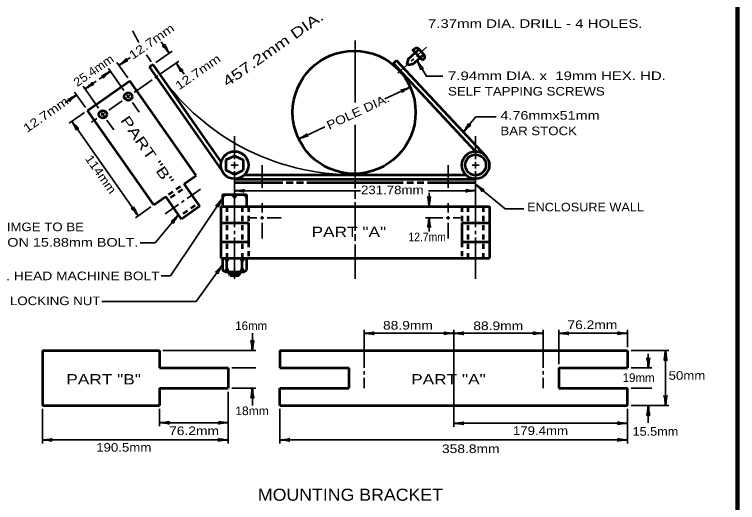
# Model space of a CAD drawing. Extents: x -33 to 680, y -7 to 447.
# Drawn here: x 464.8 to 674.8, y 130.8 to 272.6 of the extents above; entities that cross this region are included whole.
import ezdxf

# ---------------------------------------------------------------- set-up
doc = ezdxf.new("R2010")
doc.units = 0
doc.linetypes.add('SHORT_DASHED', pattern=[2.7, 1.5, -1.2])
doc.layers.add('1', color=7, linetype='Continuous', lineweight=53)

msp = doc.modelspace()

# ---------------------------------------------------------------- linework, layer by layer
at = {"layer": '1', "lineweight": 158}
msp.add_line((674.767, 2.994), (674.767, 441.411), dxfattribs=at)
at = {"layer": '1', "lineweight": 13}
msp.add_line((674.767, 2.994), (674.767, 441.411), dxfattribs=at)
at = {"layer": '1', "lineweight": 35}
for p, q in [((507.412, 264.673), (509.706, 261.396)), ((563.683, 247.071), (563.683, 265.073)), ((581.861, 260.776), (584.461, 263.118)), ((510.525, 261.97), (505.815, 258.672)), ((581.489, 260.442), (581.861, 260.776)), ((497.664, 254.185), (494.51, 258.691)), ((495.083, 257.872), (498.36, 260.166)), ((507.208, 255.375), (512.533, 259.103)), ((511.714, 258.529), (514.008, 255.253)), ((578.887, 258.099), (579.259, 258.434)), ((580.002, 259.103), (580.746, 259.772)), ((496.567, 250.522), (492.052, 256.97)), ((576.101, 255.59), (578.887, 258.099)), ((489.349, 253.857), (492.626, 256.151)), ((505.57, 254.228), (506.389, 254.801)), ((485.253, 250.989), (488.53, 253.283)), ((499.529, 249.998), (504.751, 253.654)), ((485.377, 245.582), (482.222, 250.087)), ((489.192, 245.363), (484.68, 251.808)), ((572.353, 248.101), (579.707, 251.53)), ((479.519, 246.974), (482.796, 249.268)), ((497.277, 248.421), (498.301, 249.138)), ((498.145, 248.269), (497.428, 249.293)), ((492.159, 244.837), (496.048, 247.56)), ((500.942, 244.273), (499.005, 247.04)), ((480.626, 241.034), (485.132, 244.189)), ((489.906, 243.26), (490.93, 243.977)), ((490.77, 243.11), (490.053, 244.134)), ((481.445, 241.608), (500.701, 214.108)), ((487.139, 241.322), (488.678, 242.4)), ((493.57, 239.111), (491.63, 241.882)), ((547.32, 236.428), (554.868, 239.948)), ((563.683, 226.043), (563.683, 240.605)), ((528.683, 237.293), (528.683, 230.593)), ((598.683, 237.293), (598.683, 230.593)), ((528.683, 229.843), (528.683, 227.843)), ((598.683, 229.843), (598.683, 227.843)), ((527.683, 228.843), (529.683, 228.843)), ((536.683, 222.293), (536.683, 228.793)), ((590.683, 222.293), (590.683, 228.793)), ((597.683, 228.843), (599.683, 228.843)), ((598.683, 227.093), (598.683, 210.793)), ((563.683, 226.043), (563.683, 222.043)), ((514.873, 219.148), (518.764, 221.872)), ((528.683, 221.397), (565.267, 221.397)), ((563.683, 221.043), (563.683, 219.043)), ((584.998, 221.397), (598.683, 221.397)), ((585.183, 216.793), (585.183, 220.793)), ((525.183, 219.224), (510.108, 196.647)), ((513.235, 218.001), (514.054, 218.574)), ((528.683, 220.293), (528.683, 210.793)), ((499.882, 213.534), (504.387, 216.689)), ((508.525, 214.703), (512.416, 217.427)), ((536.683, 217.793), (536.683, 215.043)), ((563.683, 218.043), (563.683, 209.793)), ((590.683, 217.793), (590.683, 215.043)), ((512.396, 214.404), (505.588, 206.275)), ((533.183, 213.543), (535.183, 213.543)), ((536.183, 213.543), (537.183, 213.543)), ((536.683, 214.043), (536.683, 213.043)), ((538.183, 213.543), (542.183, 213.543)), ((584.183, 213.543), (589.183, 213.543)), ((585.183, 213.543), (585.183, 209.543)), ((590.183, 213.543), (591.183, 213.543)), ((590.683, 214.043), (590.683, 213.043)), ((592.183, 213.543), (594.183, 213.543)), ((536.683, 212.043), (536.683, 207.543)), ((590.683, 212.043), (590.683, 207.543)), ((528.683, 209.793), (528.683, 208.793)), ((563.683, 208.793), (563.683, 206.793)), ((598.683, 209.793), (598.683, 208.793)), ((505.588, 206.275), (501.251, 206.275)), ((528.683, 207.793), (528.683, 195.793)), ((598.683, 207.793), (598.683, 195.793)), ((563.683, 205.793), (563.683, 195.793)), ((525.183, 199.873), (517.556, 189.163)), ((510.108, 196.647), (507.318, 196.647)), ((517.556, 189.163), (490.164, 189.163)), ((566.352, 180.965), (566.352, 169.965)), ((592.352, 180.965), (592.352, 152.798)), ((618.352, 180.965), (618.352, 169.965)), ((622.852, 170.965), (622.852, 180.965)), ((642.852, 175.965), (642.852, 180.965)), ((533.852, 174.965), (533.852, 179.965)), ((622.852, 179.965), (642.852, 179.965)), ((507.852, 174.965), (534.852, 174.965)), ((643.852, 174.965), (654.852, 174.965)), ((653.852, 174.965), (653.852, 158.965)), ((648.852, 173.965), (648.852, 169.965)), ((527.852, 169.965), (534.852, 169.965)), ((566.352, 168.965), (566.352, 167.965)), ((618.352, 168.965), (618.352, 167.965)), ((643.852, 169.965), (649.852, 169.965)), ((566.352, 166.965), (566.352, 163.965)), ((618.352, 166.965), (618.352, 163.965)), ((527.852, 163.965), (534.852, 163.965)), ((533.852, 163.965), (533.852, 158.965)), ((643.852, 163.965), (649.852, 163.965)), ((526.852, 162.965), (526.852, 147.965)), ((472.852, 157.965), (472.852, 147.965)), ((506.852, 157.965), (506.852, 152.965)), ((541.852, 157.965), (541.852, 147.965)), ((642.852, 157.965), (642.852, 147.965)), ((643.852, 158.965), (654.852, 158.965)), ((648.852, 158.965), (648.852, 153.965)), ((506.852, 153.965), (526.852, 153.965)), ((592.352, 153.798), (642.852, 153.798)), ((472.852, 148.965), (526.852, 148.965)), ((541.852, 148.965), (642.852, 148.965))]:
    msp.add_line(p, q, dxfattribs=at)
at = {"layer": '1'}
for p, q in [((579.135, 259.668), (582.293, 262.512)), ((580.499, 258.205), (583.658, 261.049)), ((583.658, 261.049), (582.294, 262.512)), ((574.813, 258.437), (575.727, 259.29)), ((598.683, 232.84), (574.813, 258.437)), ((601.849, 231.277), (575.727, 259.29)), ((579.135, 259.668), (578.717, 258.282)), ((583.225, 259.313), (583.746, 259.783)), ((504.996, 258.099), (503.972, 257.382)), ((524.949, 227.424), (503.972, 257.382)), ((524.817, 229.791), (504.996, 258.099)), ((579.058, 257.916), (578.717, 258.282)), ((580.499, 258.205), (579.058, 257.916)), ((485.951, 244.763), (498.238, 253.366)), ((517.494, 225.866), (498.238, 253.366)), ((505.207, 217.262), (485.951, 244.763)), ((526.183, 230.343), (526.183, 227.343)), ((531.183, 230.343), (531.183, 227.343)), ((528.683, 226.093), (526.183, 227.343)), ((528.683, 226.093), (531.183, 227.343)), ((514.012, 223.428), (517.494, 225.866)), ((528.683, 224.793), (598.683, 224.793)), ((518.601, 216.875), (514.012, 223.428)), ((528.683, 223.793), (542.683, 223.793)), ((543.683, 223.793), (545.683, 223.793)), ((546.683, 223.793), (548.683, 223.793)), ((578.683, 223.793), (580.683, 223.793)), ((581.683, 223.793), (583.683, 223.793)), ((584.683, 223.793), (598.683, 223.793)), ((505.207, 217.262), (508.688, 219.7)), ((513.276, 213.147), (508.688, 219.7)), ((525.183, 220.293), (525.183, 216.793)), ((525.183, 219.293), (525.933, 220.293)), ((531.433, 220.293), (532.183, 219.293)), ((532.183, 220.293), (532.183, 216.793)), ((518.601, 216.875), (513.276, 213.147)), ((524.683, 216.793), (602.683, 216.793)), ((524.683, 216.793), (524.683, 201.793)), ((602.683, 216.793), (602.683, 201.793)), ((524.683, 212.043), (532.683, 212.043)), ((532.683, 212.043), (532.683, 206.543)), ((594.683, 212.043), (602.683, 212.043)), ((594.683, 212.043), (594.683, 206.543)), ((524.683, 206.543), (532.683, 206.543)), ((594.683, 206.543), (602.683, 206.543)), ((524.683, 201.793), (602.683, 201.793)), ((525.183, 201.793), (525.183, 198.293)), ((532.183, 201.793), (532.183, 198.293)), ((526.433, 198.793), (526.433, 200.793)), ((530.933, 198.793), (530.933, 200.793)), ((525.183, 198.293), (525.933, 197.793)), ((525.933, 197.793), (526.933, 197.793)), ((526.933, 197.793), (530.433, 197.793)), ((527.433, 196.793), (526.933, 197.793)), ((529.933, 196.793), (530.433, 197.793)), ((530.433, 197.793), (531.433, 197.793)), ((531.433, 197.793), (532.183, 198.293)), ((527.183, 197.293), (530.183, 197.293)), ((527.433, 196.793), (529.933, 196.793)), ((472.852, 174.965), (506.852, 174.965)), ((472.852, 174.965), (472.852, 158.965)), ((506.852, 174.965), (506.852, 169.965)), ((541.852, 174.965), (541.852, 169.965)), ((541.852, 174.965), (642.852, 174.965)), ((642.852, 174.965), (642.852, 169.965)), ((506.852, 169.965), (526.852, 169.965)), ((526.852, 169.965), (526.852, 163.965)), ((541.852, 169.965), (561.852, 169.965)), ((561.852, 169.965), (561.852, 163.965)), ((622.852, 169.965), (642.852, 169.965)), ((622.852, 169.965), (622.852, 163.965)), ((506.852, 163.965), (526.852, 163.965)), ((506.852, 163.965), (506.852, 158.965)), ((541.852, 163.965), (561.852, 163.965)), ((541.852, 158.965), (541.852, 163.965)), ((622.852, 163.965), (642.852, 163.965)), ((642.852, 158.965), (642.852, 163.965)), ((472.852, 158.965), (506.852, 158.965)), ((541.852, 158.965), (642.852, 158.965))]:
    msp.add_line(p, q, dxfattribs=at)
at = {"layer": '1', "linetype": 'SHORT_DASHED'}
for p, q in [((509.507, 220.274), (513.193, 222.855)), ((510.08, 219.454), (513.767, 222.036)), ((517.208, 217.121), (513.522, 214.54)), ((526.433, 216.793), (526.433, 201.793)), ((530.933, 216.793), (530.933, 201.793)), ((532.683, 216.793), (532.683, 212.043)), ((594.683, 216.793), (594.683, 212.043)), ((596.433, 216.793), (596.433, 201.793)), ((600.933, 216.793), (600.933, 201.793)), ((532.683, 206.543), (532.683, 201.793)), ((594.683, 206.543), (594.683, 201.793))]:
    msp.add_line(p, q, dxfattribs=at)
at = {"layer": '1'}
for points in [[(583.225, 259.313), (580.496, 262.239), (581.054, 262.741)], [(526.183, 230.343), (528.683, 231.593), (531.183, 230.343)], [(531.56, 226.043), (563.683, 226.043), (595.818, 226.043)], [(549.683, 223.793), (563.683, 223.793), (577.683, 223.793)], [(525.183, 220.293), (528.683, 220.293), (532.183, 220.293)], [(527.933, 220.293), (528.683, 219.293), (529.433, 220.293)], [(525.933, 201.793), (526.433, 200.793), (526.933, 201.793)], [(530.433, 201.793), (530.933, 200.793), (531.433, 201.793)], [(525.933, 197.793), (526.433, 198.793), (526.933, 197.793)], [(530.433, 197.793), (530.933, 198.793), (531.433, 197.793)]]:
    msp.add_lwpolyline(points, dxfattribs=at)
at = {"layer": '1', "lineweight": 35}
for points in [[(581.673, 259.262), (584.398, 254.663), (589.126, 254.663)], [(595.121, 238.492), (598.79, 242.912), (604.629, 242.912)], [(528.683, 227.093), (528.683, 223.793), (528.683, 220.293)], [(598.683, 223.24), (607.284, 216.149), (612.667, 216.149)], [(566.352, 179.965), (592.352, 179.965), (618.352, 179.965)]]:
    msp.add_lwpolyline(points, dxfattribs=at)
at = {"layer": '1'}
for centre, radius in [((563.408, 244.206), 17.869), ((497.787, 248.782), 1.125), ((490.414, 243.624), 1.125), ((528.703, 228.843), 4), ((598.677, 228.84), 4), ((598.683, 228.898), 3)]:
    msp.add_circle(centre, radius, dxfattribs=at)
at = {"layer": '1', "lineweight": 35}
for centre, radius, start, end in [((567.343, 302.494), 76.539, 206.85259, 209.79059), ((567.343, 302.494), 76.539, 212.88403, 214.71143), ((562.942, 294.319), 68.281, 212.77906, 270.62148)]:
    msp.add_arc(centre, radius, start, end, dxfattribs=at)
at = {"layer": '1'}
for centre, start, end in [((581.55, 261.961), 36.55151, 122.47574), ((583.028, 260.367), 320.85592, 48.49762)]:
    msp.add_arc(centre, 0.925, start, end, dxfattribs=at)
at = {"layer": '1', "lineweight": 40}
for centre, major_axis, ratio, start_param, end_param in [((508.854, 262.132), (1.152, -1.373), 0.122415, 0.8963533, 3.1415927), ((509.237, 262.436), (-0.864, 1.54), 0.07063, 6.2823074, 8.5597026), ((495.819, 258.724), (-1.373, -1.152), 0.122415, 0.8963533, 3.1415927), ((496.122, 258.341), (1.54, 0.864), 0.07063, 6.2823074, 8.5597026), ((512.183, 257.49), (0.864, -1.54), 0.07063, 6.2823074, 8.5597026), ((512.566, 257.794), (-1.152, 1.373), 0.122415, 0.8963533, 3.1415927), ((582.062, 258.19), (-0.744, 1.601), 0.07063, 3.1407148, 5.41811), ((582.467, 258.464), (-1.045, 1.457), 0.122415, 0.8963533, 3.1415927), ((491.587, 255.682), (1.54, 0.864), 0.07063, 3.1407148, 5.41811), ((491.587, 255.682), (1.54, 0.864), 0.07063, 3.1407148, 5.41811), ((491.89, 255.299), (1.373, 1.152), 0.122415, 0.8963533, 3.1415927), ((491.89, 255.299), (1.373, 1.152), 0.122415, 0.8963533, 3.1415927), ((485.989, 251.841), (-1.373, -1.152), 0.122415, 0.8963533, 3.1415927), ((486.293, 251.458), (1.54, 0.864), 0.07063, 6.2823074, 8.5597026), ((578.602, 251.249), (-1.666, -0.583), 0.07063, 6.2823074, 8.5597026), ((578.602, 251.249), (-1.666, -0.583), 0.07063, 6.2823074, 8.5597026), ((578.835, 250.819), (1.552, 0.896), 0.122415, 0.8963533, 3.1415927), ((578.835, 250.819), (1.552, 0.896), 0.122415, 0.8963533, 3.1415927), ((481.757, 248.799), (1.54, 0.864), 0.07063, 3.1407148, 5.41811), ((482.061, 248.416), (1.373, 1.152), 0.122415, 0.8963533, 3.1415927), ((481.915, 240.569), (-0.864, 1.54), 0.07063, 3.1407148, 5.41811), ((481.915, 240.569), (-0.864, 1.54), 0.07063, 3.1407148, 5.41811), ((482.298, 240.873), (-1.152, 1.373), 0.122415, 0.8963533, 3.1415927), ((482.298, 240.873), (-1.152, 1.373), 0.122415, 0.8963533, 3.1415927), ((595.605, 239.508), (-1.021, -1.474), 0.122415, 0.8963533, 3.1415927), ((595.999, 239.219), (1.257, 1.239), 0.07063, 6.2823074, 8.5597026), ((548.193, 237.14), (-1.552, -0.896), 0.122415, 0.8963533, 3.1415927), ((548.425, 236.71), (1.666, 0.583), 0.07063, 6.2823074, 8.5597026), ((599.413, 222.364), (-1.244, 1.253), 0.07063, 3.1407148, 5.41811), ((599.7, 222.759), (-1.477, 1.015), 0.122415, 0.8963533, 3.1415927), ((529.803, 221.185), (-1.756, 0.176), 0.07063, 3.1407148, 5.41811), ((529.774, 221.673), (-1.786, -0.156), 0.122415, 0.8963533, 3.1415927), ((597.591, 221.12), (1.786, 0.156), 0.122415, 0.8963533, 3.1415927), ((597.562, 221.608), (1.756, -0.176), 0.07063, 3.1407148, 5.41811), ((524.384, 218.41), (1.121, 1.363), 0.07063, 3.1407148, 5.41811), ((524.384, 218.41), (1.121, 1.363), 0.07063, 3.1407148, 5.41811), ((524.806, 218.163), (0.862, 1.572), 0.122415, 0.8963533, 3.1415927), ((524.806, 218.163), (0.862, 1.572), 0.122415, 0.8963533, 3.1415927), ((584.906, 217.884), (0.156, -1.786), 0.122415, 0.8963533, 3.1415927), ((585.394, 217.913), (-0.176, -1.756), 0.07063, 3.1407148, 5.41811), ((500.232, 215.147), (0.864, -1.54), 0.07063, 3.1407148, 5.41811), ((499.849, 214.843), (1.152, -1.373), 0.122415, 0.8963533, 3.1415927), ((511.515, 213.681), (1.262, 1.234), 0.07063, 3.1407148, 5.41811), ((511.515, 213.681), (1.262, 1.234), 0.07063, 3.1407148, 5.41811), ((511.908, 213.39), (1.027, 1.469), 0.122415, 0.8963533, 3.1415927), ((511.908, 213.39), (1.027, 1.469), 0.122415, 0.8963533, 3.1415927), ((584.971, 212.422), (0.176, 1.756), 0.07063, 3.1407148, 5.41811), ((585.459, 212.452), (-0.156, 1.786), 0.122415, 0.8963533, 3.1415927), ((524.36, 199.083), (-1.162, -1.329), 0.07063, 6.2823074, 8.5597026), ((524.36, 199.083), (-1.162, -1.329), 0.07063, 6.2823074, 8.5597026), ((524.775, 198.824), (0.909, 1.545), 0.122415, 0.8963533, 3.1415927), ((524.775, 198.824), (0.909, 1.545), 0.122415, 0.8963533, 3.1415927), ((567.472, 179.753), (-1.756, 0.176), 0.07063, 3.1407148, 5.41811), ((567.472, 179.753), (-1.756, 0.176), 0.07063, 3.1407148, 5.41811), ((567.443, 180.241), (-1.786, -0.156), 0.122415, 0.8963533, 3.1415927), ((567.443, 180.241), (-1.786, -0.156), 0.122415, 0.8963533, 3.1415927), ((591.26, 179.689), (1.786, 0.156), 0.122415, 0.8963533, 3.1415927), ((591.26, 179.689), (1.786, 0.156), 0.122415, 0.8963533, 3.1415927), ((591.231, 180.176), (1.756, -0.176), 0.07063, 3.1407148, 5.41811), ((591.231, 180.176), (1.756, -0.176), 0.07063, 3.1407148, 5.41811), ((593.472, 179.753), (-1.756, 0.176), 0.07063, 3.1407148, 5.41811), ((593.472, 179.753), (-1.756, 0.176), 0.07063, 3.1407148, 5.41811), ((593.443, 180.241), (-1.786, -0.156), 0.122415, 0.8963533, 3.1415927), ((593.443, 180.241), (-1.786, -0.156), 0.122415, 0.8963533, 3.1415927), ((617.26, 179.689), (1.786, 0.156), 0.122415, 0.8963533, 3.1415927), ((617.26, 179.689), (1.786, 0.156), 0.122415, 0.8963533, 3.1415927), ((617.231, 180.176), (1.756, -0.176), 0.07063, 3.1407148, 5.41811), ((617.231, 180.176), (1.756, -0.176), 0.07063, 3.1407148, 5.41811), ((623.972, 179.753), (-1.756, 0.176), 0.07063, 3.1407148, 5.41811), ((623.943, 180.241), (-1.786, -0.156), 0.122415, 0.8963533, 3.1415927), ((641.76, 179.689), (1.786, 0.156), 0.122415, 0.8963533, 3.1415927), ((641.731, 180.176), (1.756, -0.176), 0.07063, 3.1407148, 5.41811), ((533.575, 176.056), (0.156, -1.786), 0.122415, 0.8963533, 3.1415927), ((534.063, 176.085), (-0.176, -1.756), 0.07063, 3.1407148, 5.41811), ((653.64, 173.844), (0.176, 1.756), 0.07063, 3.1407148, 5.41811), ((654.128, 173.874), (-0.156, 1.786), 0.122415, 0.8963533, 3.1415927), ((648.575, 171.056), (0.156, -1.786), 0.122415, 0.8963533, 3.1415927), ((649.063, 171.085), (-0.176, -1.756), 0.07063, 3.1407148, 5.41811), ((533.64, 162.844), (0.176, 1.756), 0.07063, 3.1407148, 5.41811), ((534.128, 162.874), (-0.156, 1.786), 0.122415, 0.8963533, 3.1415927), ((653.575, 160.056), (0.156, -1.786), 0.122415, 0.8963533, 3.1415927), ((654.063, 160.085), (-0.176, -1.756), 0.07063, 3.1407148, 5.41811), ((648.64, 157.844), (0.176, 1.756), 0.07063, 3.1407148, 5.41811), ((649.128, 157.874), (-0.156, 1.786), 0.122415, 0.8963533, 3.1415927), ((507.972, 153.753), (-1.756, 0.176), 0.07063, 3.1407148, 5.41811), ((507.972, 153.753), (-1.756, 0.176), 0.07063, 3.1407148, 5.41811), ((507.943, 154.241), (-1.786, -0.156), 0.122415, 0.8963533, 3.1415927), ((507.943, 154.241), (-1.786, -0.156), 0.122415, 0.8963533, 3.1415927), ((525.76, 153.689), (1.786, 0.156), 0.122415, 0.8963533, 3.1415927), ((525.76, 153.689), (1.786, 0.156), 0.122415, 0.8963533, 3.1415927), ((525.731, 154.176), (1.756, -0.176), 0.07063, 3.1407148, 5.41811), ((525.731, 154.176), (1.756, -0.176), 0.07063, 3.1407148, 5.41811), ((593.472, 153.587), (-1.756, 0.176), 0.07063, 3.1407148, 5.41811), ((593.472, 153.587), (-1.756, 0.176), 0.07063, 3.1407148, 5.41811), ((593.443, 154.074), (-1.786, -0.156), 0.122415, 0.8963533, 3.1415927), ((593.443, 154.074), (-1.786, -0.156), 0.122415, 0.8963533, 3.1415927), ((641.76, 153.522), (1.786, 0.156), 0.122415, 0.8963533, 3.1415927), ((641.76, 153.522), (1.786, 0.156), 0.122415, 0.8963533, 3.1415927), ((641.731, 154.01), (1.756, -0.176), 0.07063, 3.1407148, 5.41811), ((641.731, 154.01), (1.756, -0.176), 0.07063, 3.1407148, 5.41811), ((473.943, 149.241), (-1.786, -0.156), 0.122415, 0.8963533, 3.1415927), ((525.731, 149.176), (1.756, -0.176), 0.07063, 3.1407148, 5.41811), ((525.731, 149.176), (1.756, -0.176), 0.07063, 3.1407148, 5.41811), ((542.943, 149.241), (-1.786, -0.156), 0.122415, 0.8963533, 3.1415927), ((641.731, 149.176), (1.756, -0.176), 0.07063, 3.1407148, 5.41811), ((641.731, 149.176), (1.756, -0.176), 0.07063, 3.1407148, 5.41811), ((473.972, 148.753), (-1.756, 0.176), 0.07063, 3.1407148, 5.41811), ((525.76, 148.689), (1.786, 0.156), 0.122415, 0.8963533, 3.1415927), ((525.76, 148.689), (1.786, 0.156), 0.122415, 0.8963533, 3.1415927), ((542.972, 148.753), (-1.756, 0.176), 0.07063, 3.1407148, 5.41811), ((641.76, 148.689), (1.786, 0.156), 0.122415, 0.8963533, 3.1415927), ((641.76, 148.689), (1.786, 0.156), 0.122415, 0.8963533, 3.1415927)]:
    msp.add_ellipse(centre, major_axis=major_axis, ratio=ratio, start_param=start_param, end_param=end_param, dxfattribs=at)

# ---------------------------------------------------------------- texts
at = {"layer": '1'}
for s, height, rotation, width, p in [('457.2mm DIA.', 3, 35.001, 1.35, (526.531, 251.5)), ('12.7mm', 2.5, 35.001, 1.25, (499.092, 259.428)), ('25.4mm', 2.5, 35.001, 1.1, (482.999, 251.531)), ('12.7mm', 2.5, 35.001, 1.25, (512.557, 250.548)), ('12.7mm', 2.5, 35.001, 1.25, (468.391, 238.186)), ('POLE DIA.', 2.5, 25, 1.2, (556.155, 239.104)), ('PART "B"', 3, 305, 1.35, (495.386, 241.846)), ('114mm', 2.5, 305, 1.15, (485.124, 230.738))]:
    msp.add_text(s, height=height, rotation=rotation, dxfattribs=dict(at, width=width)).set_placement(p)
for s, height, width, p in [('7.37mm DIA. DRILL - 4 HOLES.', 2.5, 1.3, (584.858, 268.749)), ('7.94mm DIA. x  19mm HEX. HD.', 2.5, 1.3, (590.678, 253.567)), ('SELF TAPPING SCREWS', 2.5, 1.15, (590.678, 249.067)), ('4.76mmx51mm ', 2.5, 1.25, (605.902, 242.051)), ('BAR STOCK', 2.5, 1.15, (605.902, 237.551)), ('231.78mm', 2.5, 1.15, (565.401, 220.392)), ('ENCLOSURE WALL', 2.5, 1.1, (613.657, 215.399)), ('FORMED HIMGE TO BE', 2.5, 1.15, (442.014, 209.644)), ('PART "A"', 3, 1.25, (551.043, 207.939)), ('12.7mm', 2.5, 0.9, (579.173, 206.722)), ('SNUG FIT ON 15.88mm BOLT.', 2.5, 1.25, (442.014, 205.144)), ('15.88mmx63.5mm HEX. HEAD MACHINE BOLT', 2.5, 1.2, (419.77, 195.401)), ('HEX. SELF LOCKING NUT', 2.5, 1.15, (442.734, 188.143)), ('88.9mm', 2.5, 1.2, (571.795, 181.039)), ('88.9mm', 2.5, 1.2, (598.025, 180.889)), ('76.2mm', 2.5, 1.2, (625.363, 181.192)), ('PART "B"', 3, 1.25, (479.812, 165.086)), ('PART "A"', 3, 1.25, (579.967, 165.086)), ('50mm', 2.5, 1.15, (654.741, 166.447)), ('18mm', 2.5, 1.05, (528.883, 156.161)), ('76.2mm', 2.5, 1.2, (509.668, 150.369)), ('179.4mm', 2.5, 1.15, (609.517, 150.399)), ('15.5mm', 2.5, 1.1, (644.272, 150.176)), ('190.5mm', 2.5, 1.15, (488.494, 145.543)), ('358.8mm', 2.5, 1.2, (588.924, 145.137)), ('MOUNTING BRACKET', 3.5, 1.1, (535.454, 131.286))]:
    msp.add_text(s, height=height, dxfattribs=dict(at, width=width)).set_placement(p)
for s, p in [('16mm', (528.883, 180.907)), ('19mm', (641.392, 165.807))]:
    msp.add_text(s, height=2.5, dxfattribs=at).set_placement(p)

doc.saveas('drawing.dxf')
